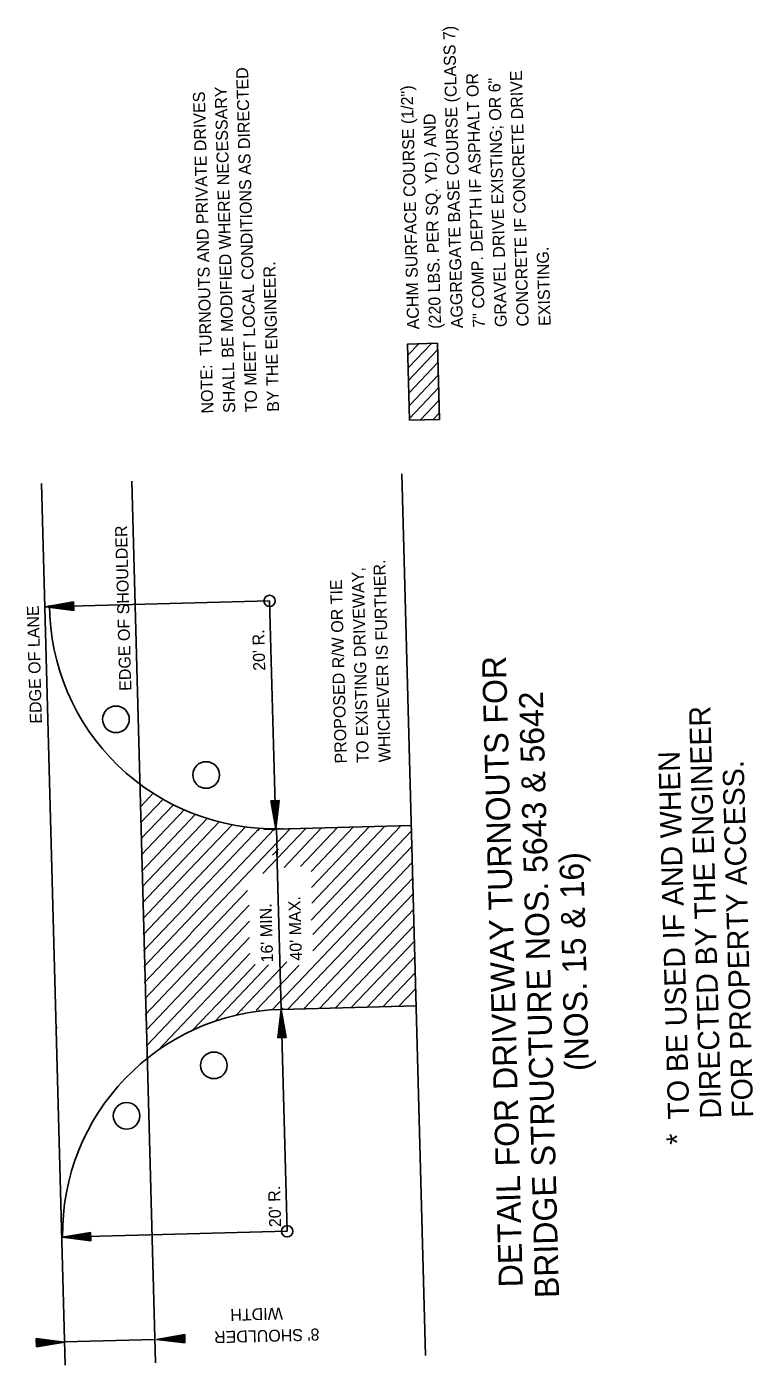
# Model space of a CAD drawing. Extents: x 1929624 to 1936506, y 596315 to 605721.
# Drawn here: x 1931746 to 1932155, y 604966 to 605721 of the extents above; entities that cross this region are included whole.
import ezdxf

# ---------------------------------------------------------------- set-up
doc = ezdxf.new("R2010")
doc.units = 0
for name, color, linetype in [('Default', 7, 'Continuous'), ('Level 47', 7, 'Continuous'), ('R_Border', 7, 'Continuous')]:
    doc.layers.add(name, color=color, linetype=linetype)

msp = doc.modelspace()

# ---------------------------------------------------------------- linework, layer by layer
at = {"layer": 'Default'}
for p, q in [((1931767.59, 604965.99), (1931754.24, 605463.11)), ((1931818.4, 604967.35), (1931805.06, 605464.47)), ((1931970.56, 604971.44), (1931957.22, 605468.56)), ((1931882.72, 605396.92), (1931756.42, 605393.53)), ((1931772.26, 605396.34), (1931756.42, 605393.53)), ((1931772.28, 605395.92), (1931759.13, 605393.6)), ((1931772.29, 605395.52), (1931761.84, 605393.67)), ((1931772.3, 605395.12), (1931764.47, 605393.74)), ((1931772.31, 605394.73), (1931767.19, 605393.81)), ((1931772.32, 605394.33), (1931769.83, 605393.89)), ((1931772.39, 605391.56), (1931772.26, 605396.34)), ((1931886.17, 605268.42), (1931882.72, 605396.92)), ((1931772.39, 605391.56), (1931756.42, 605393.53)), ((1931772.38, 605391.94), (1931759.13, 605393.6)), ((1931772.37, 605392.34), (1931761.84, 605393.67)), ((1931772.36, 605392.74), (1931764.47, 605393.74)), ((1931772.35, 605393.15), (1931767.19, 605393.81)), ((1931772.34, 605393.54), (1931769.83, 605393.89)), ((1931888.09, 605284.35), (1931883.36, 605284.22)), ((1931883.36, 605284.22), (1931886.17, 605268.42)), ((1931883.73, 605284.23), (1931886.1, 605271.07)), ((1931884.13, 605284.24), (1931886.03, 605273.81)), ((1931884.54, 605284.25), (1931885.96, 605276.43)), ((1931884.92, 605284.26), (1931885.88, 605279.13)), ((1931885.37, 605284.27), (1931885.81, 605281.77)), ((1931886.13, 605284.29), (1931885.81, 605281.77)), ((1931886.49, 605284.3), (1931885.88, 605279.13)), ((1931886.89, 605284.32), (1931885.96, 605276.43)), ((1931887.32, 605284.33), (1931886.03, 605273.81)), ((1931887.72, 605284.34), (1931886.1, 605271.07)), ((1931888.09, 605284.35), (1931886.17, 605268.42)), ((1931837.79, 605227.35), (1931877.1, 605268.7)), ((1931838.17, 605209.48), (1931894.21, 605268.43)), ((1931853.04, 605252.52), (1931869.15, 605269.48)), ((1931873.44, 605255.71), (1931885.3, 605268.19)), ((1931878.95, 605243.22), (1931903.12, 605268.66)), ((1931879.2, 605268.02), (1931886.45, 605268.22)), ((1931962.67, 605270.26), (1931886.18, 605268.21)), ((1931886.91, 605253.68), (1931886.5, 605268.79)), ((1931890.88, 605246.64), (1931912.03, 605268.9)), ((1931900.12, 605247.23), (1931920.95, 605269.14)), ((1931906.03, 605216.91), (1931956.6, 605270.1)), ((1931906.04, 605244.32), (1931929.86, 605269.38)), ((1931906.27, 605235.4), (1931938.77, 605269.62)), ((1931906.49, 605226.5), (1931947.7, 605269.86)), ((1931907.1, 605208.87), (1931962.62, 605267.28)), ((1931906.99, 605199.61), (1931962.86, 605258.38)), ((1931889.25, 605166.58), (1931886.84, 605256.18)), ((1931884.12, 605166.44), (1931963.1, 605249.51)), ((1931893.03, 605166.68), (1931963.34, 605240.62)), ((1931901.96, 605166.92), (1931963.57, 605231.72)), ((1931910.87, 605167.16), (1931963.81, 605222.84)), ((1931919.79, 605167.4), (1931964.05, 605213.94)), ((1931928.72, 605167.63), (1931964.29, 605205.07)), ((1931851.8, 605159.84), (1931882.12, 605191.72)), ((1931857.89, 605174.34), (1931874.59, 605191.92)), ((1931863.78, 605163.3), (1931892.36, 605193.38)), ((1931875.21, 605166.2), (1931899.28, 605191.51)), ((1931937.62, 605167.87), (1931964.53, 605196.19)), ((1931946.54, 605168.11), (1931964.77, 605187.29)), ((1931955.44, 605168.35), (1931965.01, 605178.42)), ((1931889.25, 605166.58), (1931965.27, 605168.62)), ((1931883.65, 605166.42), (1931889.58, 605166.58)), ((1931887.32, 605150.63), (1931889.25, 605166.58)), ((1931887.68, 605150.64), (1931889.32, 605163.89)), ((1931888.1, 605150.65), (1931889.39, 605161.18)), ((1931892.08, 605150.76), (1931889.25, 605166.58)), ((1931889.25, 605166.58), (1931892.61, 605041.5)), ((1931891.71, 605150.75), (1931889.32, 605163.89)), ((1931891.28, 605150.74), (1931889.39, 605161.18)), ((1931763.01, 605156.31), (1931762.31, 605156.52)), ((1931762.53, 605156.52), (1931763.01, 605156.31)), ((1931763.01, 605156.31), (1931762.78, 605156.53)), ((1931888.56, 605150.66), (1931889.46, 605158.53)), ((1931888.91, 605150.67), (1931889.54, 605155.83)), ((1931889.31, 605150.68), (1931889.61, 605153.18)), ((1931890.88, 605150.73), (1931889.46, 605158.53)), ((1931890.48, 605150.72), (1931889.54, 605155.83)), ((1931890.07, 605150.7), (1931889.61, 605153.18)), ((1931887.32, 605150.63), (1931892.08, 605150.76)), ((1931892.61, 605041.5), (1931766.06, 605038.1)), ((1931781.87, 605040.89), (1931766.06, 605038.1)), ((1931781.88, 605040.51), (1931768.73, 605038.18)), ((1931781.89, 605040.1), (1931771.46, 605038.25)), ((1931781.91, 605039.68), (1931774.08, 605038.32)), ((1931782, 605036.14), (1931781.87, 605040.89)), ((1931782, 605036.14), (1931766.06, 605038.1)), ((1931781.99, 605036.52), (1931768.73, 605038.18)), ((1931781.98, 605036.92), (1931771.46, 605038.25)), ((1931781.97, 605037.32), (1931774.08, 605038.32)), ((1931781.92, 605039.3), (1931776.79, 605038.39)), ((1931781.96, 605037.77), (1931776.79, 605038.39)), ((1931781.93, 605038.91), (1931779.44, 605038.46)), ((1931781.95, 605038.14), (1931779.44, 605038.46)), ((1931751.26, 604981.05), (1931767.24, 604979.08)), ((1931751.26, 604981.05), (1931751.39, 604976.27)), ((1931751.27, 604980.67), (1931764.59, 604979.01)), ((1931751.28, 604980.27), (1931761.86, 604978.94)), ((1931751.29, 604979.83), (1931759.2, 604978.87)), ((1931751.31, 604979.4), (1931756.49, 604978.79)), ((1931751.31, 604979.03), (1931753.9, 604978.72)), ((1931751.38, 604976.64), (1931764.59, 604979.01)), ((1931751.39, 604976.27), (1931767.24, 604979.08)), ((1931818.05, 604980.51), (1931767.23, 604979.15)), ((1931834.9, 604983.39), (1931819.06, 604980.57)), ((1931835.03, 604978.62), (1931819.06, 604980.57)), ((1931834.91, 604982.98), (1931821.77, 604980.64)), ((1931835.02, 604979.02), (1931821.77, 604980.64)), ((1931834.92, 604982.61), (1931824.47, 604980.71)), ((1931835.01, 604979.43), (1931824.47, 604980.71)), ((1931834.94, 604982.15), (1931827.11, 604980.79)), ((1931835, 604979.8), (1931827.11, 604980.79)), ((1931834.95, 604981.78), (1931829.83, 604980.86)), ((1931834.99, 604980.24), (1931829.83, 604980.86)), ((1931834.96, 604981.38), (1931832.46, 604980.93)), ((1931834.98, 604980.63), (1931832.46, 604980.93)), ((1931835.03, 604978.62), (1931834.9, 604983.39)), ((1931751.34, 604978.28), (1931753.9, 604978.72)), ((1931751.35, 604977.88), (1931756.49, 604978.79)), ((1931751.36, 604977.49), (1931759.2, 604978.87)), ((1931751.37, 604977.09), (1931761.86, 604978.94))]:
    msp.add_line(p, q, dxfattribs=at)
msp.add_lwpolyline([(1931961.58, 605498.82), (1931978.38, 605499.27), (1931977.23, 605542.12), (1931960.43, 605541.67)], close=True, dxfattribs=at)
for points in [[(1931960.59, 605535.43), (1931966.72, 605541.84)], [(1931960.79, 605528.32), (1931973.81, 605542.03)], [(1931960.98, 605521.18), (1931977.32, 605538.43)], [(1931961.17, 605514.04), (1931977.52, 605531.29)], [(1931961.36, 605506.93), (1931977.71, 605524.18)], [(1931961.55, 605499.81), (1931977.9, 605517.06)], [(1931967.73, 605498.98), (1931978.09, 605509.94)], [(1931974.88, 605499.18), (1931978.28, 605502.8)], [(1931809.99, 605280.88), (1931817.15, 605288.44)], [(1931809.97, 605271.7), (1931822.67, 605285.09)], [(1931810.21, 605262.68), (1931828.5, 605281.98)], [(1931810.41, 605253.64), (1931834.52, 605279.12)], [(1931810.65, 605244.62), (1931840.81, 605276.56)], [(1931810.89, 605235.63), (1931847.48, 605274.27)], [(1931811.07, 605226.6), (1931854.36, 605272.3)], [(1931837.44, 605245.25), (1931861.63, 605270.69)], [(1931866.8, 605267), (1931867.48, 605267.71)], [(1931875.9, 605267.27), (1931876.88, 605268.33)], [(1931884.9, 605267.53), (1931885.48, 605268.19)], [(1931889.41, 605268.06), (1931890.1, 605268.83)], [(1931811.48, 605208.63), (1931853.04, 605252.52)], [(1931811.95, 605190.53), (1931873.51, 605255.64)], [(1931884.43, 605253.61), (1931887.65, 605256.97)], [(1931811.28, 605217.59), (1931837.44, 605245.27)], [(1931812.34, 605172.51), (1931870.2, 605233.61)], [(1931811.71, 605199.53), (1931837.93, 605227.22)], [(1931812.54, 605163.52), (1931871.23, 605225.44)], [(1931813.36, 605155.14), (1931871.38, 605216.42)], [(1931812.12, 605181.53), (1931838.41, 605209.25)], [(1931813.6, 605146.18), (1931871.45, 605207.18)], [(1931819.96, 605143.65), (1931871.64, 605198.13)], [(1931839.31, 605154.82), (1931857.89, 605174.34)], [(1931867.4, 605165.99), (1931867.65, 605166.24)], [(1931876.38, 605166.23), (1931876.64, 605166.42)], [(1931885.31, 605166.4), (1931885.55, 605166.62)], [(1931889.67, 605166.73), (1931890.3, 605167.39)]]:
    msp.add_lwpolyline(points, dxfattribs=at)
for centre in [(1931882.71, 605396.9), (1931892.61, 605041.49)]:
    msp.add_circle(centre, 3.18, dxfattribs=at)
for centre, radius, start, end in [((1931885.52, 605395.23), 126.82, 180.29147, 271.53769), ((1931892.82, 605039.9), 126.76, 91.61408, 180.81198)]:
    msp.add_arc(centre, radius, start, end, dxfattribs=at)
at = {"layer": 'Level 47'}
for centre in [(1931796.16, 605330.15), (1931846.93, 605298.76), (1931851.33, 605135.05), (1931802.16, 605106.62)]:
    msp.add_circle(centre, 7.5, dxfattribs=at)

# ---------------------------------------------------------------- texts
at = {"layer": 'Default'}
for s, height, rotation, p in [('AGGREGATE BASE COURSE (CLASS 7)', 6.75, 91.53769, (1931991.67, 605550.7)), ('TO MEET LOCAL CONDITIONS AS DIRECTED', 6.75, 91.53769, (1931875.76, 605503.3)), ('7" COMP. DEPTH IF ASPHALT OR', 6.75, 91.53769, (1932004.01, 605551.03)), ('GRAVEL DRIVE EXISTING; OR 6"', 6.75, 91.53769, (1932016.36, 605551.37)), ('CONCRETE IF CONCRETE DRIVE', 6.75, 91.53769, (1932028.7, 605551.7)), ('NOTE:  TURNOUTS AND PRIVATE DRIVES', 6.75, 91.53769, (1931851.08, 605502.64)), ('SHALL BE MODIFIED WHERE NECESSARY', 6.75, 91.53769, (1931863.42, 605502.97)), ('ACHM SURFACE COURSE (1/2") ', 6.75, 91.53769, (1931966.99, 605550.04)), ('(220 LBS. PER SQ. YD.) AND ', 6.75, 91.53769, (1931979.33, 605550.37)), ('EXISTING.', 6.75, 91.53769, (1932041.04, 605552.03)), ('BY THE ENGINEER.', 6.75, 91.53769, (1931888.11, 605503.63)), ('EDGE OF SHOULDER', 6.75, 91.53769, (1931804.87, 605346.27)), ('WHICHEVER IS FURTHER.', 6.75, 91.53769, (1931950.93, 605306.01)), ('TO EXISTING DRIVEWAY,', 6.75, 91.53769, (1931938.58, 605305.68)), ('PROPOSED R/W OR TIE', 6.75, 91.53769, (1931926.24, 605305.35)), ('EDGE OF LANE', 6.75, 91.53769, (1931754.46, 605327.79)), ("20' R.", 6.75, 91.53769, (1931880.29, 605357.6)), ('DETAIL FOR DRIVEWAY TURNOUTS FOR', 13.5, 91.53769, (1932025.37, 605010.1)), ('BRIDGE STRUCTURE NOS. 5643 & 5642', 13.5, 91.53769, (1932045.81, 605004.05)), (' (NOS. 15 & 16)', 13.5, 91.53769, (1932062.8, 605127.03)), ("40' MAX.", 6.75, 91.53769, (1931900.96, 605194.19)), ("16' MIN.", 6.75, 91.53769, (1931884.69, 605193.14)), ("20' R.", 6.75, 91.53769, (1931889.23, 605043.94)), ('WIDTH', 6.75, 181.53769, (1931890.04, 604998.51)), ("8' SHOULDER", 6.75, 181.53769, (1931910.69, 604986.71))]:
    msp.add_text(s, height=height, rotation=rotation, dxfattribs=at).set_placement(p)
at = {"layer": 'R_Border'}
for s, p in [('DIRECTED BY THE ENGINEER', (1932137.16, 605105.2)), ('TO BE USED IF AND WHEN', (1932119.16, 605104.72)), ('FOR PROPERTY ACCESS.', (1932155.15, 605105.69)), ('*', (1932118.35, 605090.54))]:
    msp.add_text(s, height=12, rotation=91.53769, dxfattribs=at).set_placement(p)

doc.saveas('drawing.dxf')
